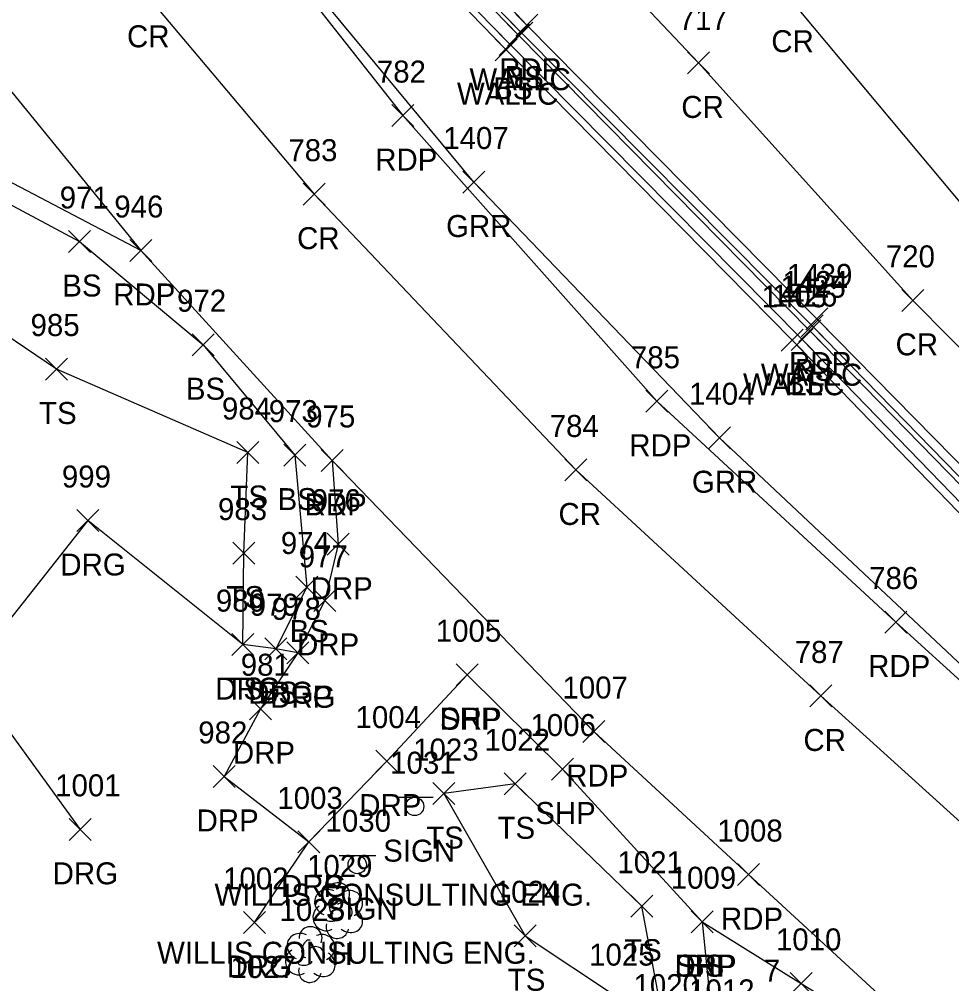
# Model space of a CAD drawing. Extents: x 1647133 to 1649138, y 411736 to 414924.
# Drawn here: x 1648689 to 1648773.8, y 411978.2 to 412065.9 of the extents above; entities that cross this region are included whole.
import ezdxf

# ---------------------------------------------------------------- set-up
doc = ezdxf.new("R2010")
doc.units = 0
for name, color, linetype in [('C_I', 7, 'Continuous'), ('L_A', 7, 'Continuous'), ('L_I', 7, 'Continuous'), ('L_TIC', 7, 'Continuous'), ('LELB', 7, 'Continuous'), ('LTD', 7, 'Continuous'), ('LW', 7, 'Continuous'), ('P_A', 7, 'Continuous'), ('P_I', 7, 'Continuous'), ('P_TIC', 7, 'Continuous'), ('PET', 7, 'Continuous'), ('PRC', 7, 'Continuous'), ('PSP', 7, 'Continuous'), ('R_A', 7, 'Continuous'), ('R_I', 7, 'Continuous'), ('R_TIC', 7, 'Continuous'), ('RDG', 7, 'Continuous'), ('RDP', 7, 'Continuous'), ('RGR', 7, 'Continuous'), ('S_A', 7, 'Continuous'), ('S_C', 7, 'Continuous'), ('S_I', 7, 'Continuous'), ('SSGN', 7, 'Continuous')]:
    doc.layers.add(name, color=color, linetype=linetype)

msp = doc.modelspace()

# ---------------------------------------------------------------- linework, layer by layer
at = {"layer": 'L_TIC'}
for points in [[(1648733.403, 412063.434), (1648735.403, 412065.434)], [(1648735.403, 412063.434), (1648733.403, 412065.434)], [(1648733.698, 412063.622), (1648735.698, 412065.622)], [(1648735.698, 412063.622), (1648733.698, 412065.622)], [(1648732.652, 412062.604), (1648734.652, 412064.604)], [(1648734.652, 412062.604), (1648732.652, 412064.604)], [(1648732.27, 412062.116), (1648734.27, 412064.116)], [(1648734.27, 412062.116), (1648732.27, 412064.116)], [(1648693.49, 412044.675), (1648695.49, 412046.675)], [(1648695.49, 412044.675), (1648693.49, 412046.675)], [(1648760.086, 412036.999), (1648762.086, 412038.999)], [(1648762.086, 412036.999), (1648760.086, 412038.999)], [(1648759.897, 412036.563), (1648761.897, 412038.563)], [(1648761.897, 412036.563), (1648759.897, 412038.563)], [(1648704.723, 412035.291), (1648706.723, 412037.291)], [(1648706.723, 412035.291), (1648704.723, 412037.291)], [(1648758.271, 412035.695), (1648760.271, 412037.695)], [(1648760.271, 412035.695), (1648758.271, 412037.695)], [(1648759.182, 412035.756), (1648761.182, 412037.756)], [(1648761.182, 412035.756), (1648759.182, 412037.756)], [(1648691.408, 412033.081), (1648693.408, 412035.081)], [(1648693.408, 412033.081), (1648691.408, 412035.081)], [(1648708.804, 412025.49), (1648710.804, 412027.49)], [(1648710.804, 412025.49), (1648708.804, 412027.49)], [(1648713.06, 412025.254), (1648715.06, 412027.254)], [(1648715.06, 412025.254), (1648713.06, 412027.254)], [(1648708.445, 412016.344), (1648710.445, 412018.344)], [(1648710.445, 412016.344), (1648708.445, 412018.344)], [(1648714.16, 412013.261), (1648716.16, 412015.261)], [(1648716.16, 412013.261), (1648714.16, 412015.261)], [(1648708.342, 412008.024), (1648710.342, 412010.024)], [(1648710.342, 412008.024), (1648708.342, 412010.024)], [(1648711.342, 412007.654), (1648713.342, 412009.654)], [(1648713.342, 412007.654), (1648711.342, 412009.654)], [(1648733.084, 411995.367), (1648735.084, 411997.367)], [(1648735.084, 411995.367), (1648733.084, 411997.367)], [(1648726.6, 411994.482), (1648728.6, 411996.482)], [(1648728.6, 411994.482), (1648726.6, 411996.482)], [(1648744.598, 411984.241), (1648746.598, 411986.241)], [(1648746.598, 411984.241), (1648744.598, 411986.241)], [(1648750.095, 411982.828), (1648752.095, 411984.828)], [(1648752.095, 411982.828), (1648750.095, 411984.828)], [(1648734.017, 411981.551), (1648736.017, 411983.551)], [(1648736.017, 411981.551), (1648734.017, 411983.551)], [(1648759.092, 411977.22), (1648761.092, 411979.22)], [(1648761.092, 411977.22), (1648759.092, 411979.22)]]:
    msp.add_lwpolyline(points, dxfattribs=at)
at = {"layer": 'LELB'}
for points in [[(1648695.678, 412105.565), (1648703.852, 412095.255), (1648710.046, 412087.718), (1648733.652, 412063.604), (1648760.182, 412036.756), (1648786.341, 412009.779), (1648811.728, 411984.211), (1648827.527, 411968.324), (1648831.218, 411963.386)], [(1648704.664, 412095.833), (1648711.149, 412088.766), (1648734.698, 412064.622), (1648761.086, 412037.999), (1648787.653, 412010.792), (1648812.355, 411985.321), (1648827.903, 411969.607)], [(1648661.044, 412062.283), (1648673.216, 412057.037), (1648694.49, 412045.675), (1648705.723, 412036.291), (1648714.06, 412026.254), (1648715.16, 412014.261), (1648712.342, 412008.654)], [(1648709.342, 412009.024), (1648709.445, 412017.344), (1648709.804, 412026.49), (1648692.408, 412034.081), (1648676.484, 412044.815), (1648662.935, 412050.112)], [(1648735.867, 411960.961), (1648741.091, 411963.551), (1648745.573, 411967.62), (1648747.716, 411974.063), (1648745.598, 411985.241), (1648734.084, 411996.367), (1648727.6, 411995.482), (1648735.017, 411982.551), (1648743.595, 411976.838)], [(1648751.095, 411983.828), (1648760.092, 411978.22), (1648771.973, 411970.92), (1648795.546, 411950.439), (1648830.258, 411918.417), (1648852.646, 411898.353), (1648868.763, 411879.164), (1648878.386, 411860.923), (1648891.378, 411855.434), (1648912.798, 411838.201), (1648926.61, 411828.098), (1648926.491, 411825.939), (1648922.273, 411828.096)]]:
    msp.add_lwpolyline(points, dxfattribs=at)
at = {"layer": 'LTD'}
for p, q in [((1648717.955, 411984.897), (1648717.955, 411984.897)), ((1648717.955, 411984.897), (1648717.955, 411984.897)), ((1648715.448, 411980.899), (1648715.448, 411980.899)), ((1648715.448, 411980.899), (1648715.448, 411980.899))]:
    msp.add_line(p, q, dxfattribs=at)
for centre in [(1648718.001, 411986.331), (1648715.494, 411982.333)]:
    msp.add_arc(centre, 1.047, 335.52715, 180.95627, dxfattribs=at)
for centre, major_axis, ratio, start_param, end_param in [((1648717.163, 411985.564), (1.21, -0.512), 0.895232, 1.570796, 4.712389), ((1648717.746, 411985.356), (-0.208, -0.792), 0.645439, 3.141593, 6.283185), ((1648718.996, 411985.481), (-1.141, -0.483), 0.949671, 1.570796, 4.712389), ((1648716.872, 411984.189), (0.584, -1.042), 0.959034, 3.141593, 6.283185), ((1648718.455, 411984.731), (-0.5, 0.667), 0.989748, 3.141593, 6.283185), ((1648718.955, 411984.064), (-1.09, 0.792), 0.841452, 1.570796, 4.712389), ((1648717.955, 411983.397), (0.265, 1.061), 0.942809, 1.570796, 4.712389), ((1648717.497, 411984.147), (-0.625, -0.083), 0.423636, 0, 3.141593), ((1648714.656, 411981.565), (1.21, -0.512), 0.895232, 1.570796, 4.712389), ((1648716.489, 411981.482), (-1.141, -0.483), 0.949671, 1.570796, 4.712389), ((1648715.239, 411981.357), (-0.208, -0.792), 0.645439, 3.141593, 6.283185), ((1648714.364, 411980.19), (0.584, -1.042), 0.959034, 3.141593, 6.283185), ((1648715.948, 411980.732), (-0.5, 0.667), 0.989748, 3.141593, 6.283185), ((1648716.448, 411980.066), (-1.09, 0.792), 0.841452, 1.570796, 4.712389), ((1648714.989, 411980.149), (-0.625, -0.083), 0.423636, 0, 3.141593), ((1648715.448, 411979.399), (0.265, 1.061), 0.942809, 1.570796, 4.712389)]:
    msp.add_ellipse(centre, major_axis=major_axis, ratio=ratio, start_param=start_param, end_param=end_param, dxfattribs=at)
at = {"layer": 'LW'}
for points in [[(1648830.392, 411963.284), (1648792.891, 412001.948), (1648759.271, 412036.695), (1648733.27, 412063.116), (1648709.494, 412087.59), (1648704.253, 412093.509), (1648697.556, 412102.144)], [(1648704.664, 412095.833), (1648710.908, 412088.591), (1648734.403, 412064.434), (1648760.897, 412037.563), (1648787.2, 412010.572), (1648812.273, 411985.189), (1648827.903, 411969.607)]]:
    msp.add_lwpolyline(points, dxfattribs=at)
at = {"layer": 'P_TIC'}
for points in [[(1648734.153, 412064.343), (1648736.153, 412066.343)], [(1648736.153, 412064.343), (1648734.153, 412066.343)], [(1648749.767, 412060.914), (1648751.767, 412062.914)], [(1648751.767, 412060.914), (1648749.767, 412062.914)], [(1648722.887, 412056.125), (1648724.887, 412058.125)], [(1648724.887, 412056.125), (1648722.887, 412058.125)], [(1648714.839, 412048.98), (1648716.839, 412050.98)], [(1648716.839, 412048.98), (1648714.839, 412050.98)], [(1648699.073, 412043.859), (1648701.073, 412045.859)], [(1648701.073, 412043.859), (1648699.073, 412045.859)], [(1648699.073, 412043.859), (1648701.073, 412045.859)], [(1648701.073, 412043.859), (1648699.073, 412045.859)], [(1648769.244, 412039.325), (1648771.244, 412041.325)], [(1648771.244, 412039.325), (1648769.244, 412041.325)], [(1648760.506, 412037.635), (1648762.506, 412039.635)], [(1648762.506, 412037.635), (1648760.506, 412039.635)], [(1648745.982, 412030.15), (1648747.982, 412032.15)], [(1648747.982, 412030.15), (1648745.982, 412032.15)], [(1648716.467, 412024.769), (1648718.467, 412026.769)], [(1648718.467, 412024.769), (1648716.467, 412026.769)], [(1648738.601, 412023.905), (1648740.601, 412025.905)], [(1648740.601, 412023.905), (1648738.601, 412025.905)], [(1648767.696, 412010.078), (1648769.696, 412012.078)], [(1648769.696, 412010.078), (1648767.696, 412012.078)], [(1648728.734, 412005.286), (1648730.734, 412007.286)], [(1648730.734, 412005.286), (1648728.734, 412007.286)], [(1648760.868, 412003.355), (1648762.868, 412005.355)], [(1648762.868, 412003.355), (1648760.868, 412005.355)], [(1648740.246, 412000.123), (1648742.246, 412002.123)], [(1648742.246, 412000.123), (1648740.246, 412002.123)], [(1648737.387, 411996.711), (1648739.387, 411998.711)], [(1648739.387, 411996.711), (1648737.387, 411998.711)], [(1648754.318, 411987.116), (1648756.318, 411989.116)], [(1648756.318, 411987.116), (1648754.318, 411989.116)], [(1648750.095, 411982.828), (1648752.095, 411984.828)], [(1648752.095, 411982.828), (1648750.095, 411984.828)]]:
    msp.add_lwpolyline(points, dxfattribs=at)
at = {"layer": 'PET'}
for points in [[(1648536.119, 412432.998), (1648543.399, 412417.954), (1648546.486, 412415.003), (1648562.248, 412380.849), (1648562.337, 412375.739), (1648565.289, 412369.171), (1648579.297, 412340.19), (1648594.414, 412306.778), (1648606.351, 412280.635), (1648620.629, 412249.259), (1648631.777, 412225.06), (1648641.267, 412204.566), (1648646.814, 412192.55), (1648664.816, 412155.812), (1648677.431, 412126.914), (1648681.854, 412118.139), (1648693.972, 412097.362), (1648709.507, 412075.411), (1648723.887, 412057.125), (1648746.982, 412031.15), (1648768.696, 412011.078), (1648794.521, 411987.621), (1648826.406, 411959.789)], [(1648512.544, 412422.792), (1648530.09, 412384.206), (1648549.578, 412341.858), (1648567.717, 412302.186), (1648584.888, 412264.911), (1648603.961, 412222.556), (1648616.989, 412192.513), (1648626.592, 412174.015), (1648634.702, 412156.346), (1648647.722, 412129.202), (1648659.195, 412106.441), (1648667.013, 412092.615), (1648674.657, 412079.411), (1648685.658, 412062.516), (1648700.073, 412044.859), (1648717.467, 412025.769), (1648741.246, 412001.123), (1648755.318, 411988.116), (1648772.85, 411971.957)], [(1648833.709, 411965.976), (1648813.189, 411986.13), (1648788.104, 412011.597), (1648761.506, 412038.635), (1648735.153, 412065.343), (1648710.962, 412091.103), (1648695.849, 412110.74)], [(1648700.073, 412044.859), (1648679.944, 412055.42), (1648661.723, 412064.182), (1648648.389, 412067.638), (1648630.86, 412074.167)]]:
    msp.add_lwpolyline(points, dxfattribs=at)
at = {"layer": 'PRC'}
for points in [[(1648523.855, 412428.164), (1648541.762, 412388.819), (1648560.786, 412347.218), (1648578.952, 412307.656), (1648596.522, 412268.849), (1648615.514, 412228.06), (1648629.383, 412198.525), (1648645.407, 412164.541), (1648659.578, 412134.14), (1648672.041, 412110.748), (1648683.898, 412091.11), (1648700.383, 412068.335), (1648715.839, 412049.98), (1648739.601, 412024.905), (1648761.868, 412004.355), (1648787.636, 411981.064), (1648820.993, 411950.624), (1648837.381, 411936.249), (1648865.129, 411910.894), (1648893.845, 411885.618), (1648930.35, 411852.903), (1648951.421, 411834.103), (1648988.1, 411800.425), (1649025.041, 411766.663)], [(1648664.816, 412155.812), (1648676.979, 412144.697), (1648692.804, 412127.015), (1648705.779, 412111.7), (1648725.575, 412089.279), (1648736.199, 412077.337), (1648750.767, 412061.914), (1648770.244, 412040.325), (1648787.372, 412023.03), (1648802.926, 412006.988), (1648820.913, 411988.588), (1648839.835, 411968.01), (1648856.098, 411949.207), (1648864.815, 411933.931), (1648873.225, 411921.132)], [(1648743.955, 412085.872), (1648758.948, 412067.89), (1648776.375, 412047.027), (1648792.583, 412027.973)]]:
    msp.add_lwpolyline(points, dxfattribs=at)
at = {"layer": 'PSP'}
msp.add_lwpolyline([(1648729.734, 412006.286), (1648738.387, 411997.711), (1648751.095, 411983.828)], dxfattribs=at)
at = {"layer": 'R_TIC'}
for points in [[(1648729.332, 412050.085), (1648731.332, 412052.085)], [(1648731.332, 412050.085), (1648729.332, 412052.085)], [(1648751.672, 412026.834), (1648753.672, 412028.834)], [(1648753.672, 412026.834), (1648751.672, 412028.834)], [(1648716.467, 412024.769), (1648718.467, 412026.769)], [(1648718.467, 412024.769), (1648716.467, 412026.769)], [(1648694.263, 412019.308), (1648696.263, 412021.308)], [(1648696.263, 412019.308), (1648694.263, 412021.308)], [(1648717.015, 412017.154), (1648719.015, 412019.154)], [(1648719.015, 412017.154), (1648717.015, 412019.154)], [(1648715.784, 412012.046), (1648717.784, 412014.046)], [(1648717.784, 412012.046), (1648715.784, 412014.046)], [(1648708.342, 412008.024), (1648710.342, 412010.024)], [(1648710.342, 412008.024), (1648708.342, 412010.024)], [(1648711.342, 412007.654), (1648713.342, 412009.654)], [(1648713.342, 412007.654), (1648711.342, 412009.654)], [(1648713.335, 412007.279), (1648715.335, 412009.279)], [(1648715.335, 412007.279), (1648713.335, 412009.279)], [(1648713.335, 412007.279), (1648715.335, 412009.279)], [(1648715.335, 412007.279), (1648713.335, 412009.279)], [(1648728.734, 412005.286), (1648730.734, 412007.286)], [(1648730.734, 412005.286), (1648728.734, 412007.286)], [(1648709.949, 412002.193), (1648711.949, 412004.193)], [(1648711.949, 412002.193), (1648709.949, 412004.193)], [(1648721.439, 411997.432), (1648723.439, 411999.432)], [(1648723.439, 411997.432), (1648721.439, 411999.432)], [(1648706.651, 411996.036), (1648708.651, 411998.036)], [(1648708.651, 411996.036), (1648706.651, 411998.036)], [(1648693.565, 411991.229), (1648695.565, 411993.229)], [(1648695.565, 411991.229), (1648693.565, 411993.229)], [(1648714.327, 411990.08), (1648716.327, 411992.08)], [(1648716.327, 411990.08), (1648714.327, 411992.08)], [(1648714.327, 411990.08), (1648716.327, 411992.08)], [(1648716.327, 411990.08), (1648714.327, 411992.08)], [(1648709.392, 411982.76), (1648711.392, 411984.76)], [(1648711.392, 411982.76), (1648709.392, 411984.76)], [(1648750.095, 411982.828), (1648752.095, 411984.828)], [(1648752.095, 411982.828), (1648750.095, 411984.828)]]:
    msp.add_lwpolyline(points, dxfattribs=at)
at = {"layer": 'RDG'}
for points in [[(1648714.335, 412008.279), (1648712.342, 412008.654), (1648709.342, 412009.024), (1648695.263, 412020.308), (1648684.257, 412006.407), (1648694.565, 411992.229)], [(1648710.392, 411983.76), (1648715.327, 411991.08)]]:
    msp.add_lwpolyline(points, dxfattribs=at)
at = {"layer": 'RDP'}
for points in [[(1648717.467, 412025.769), (1648718.015, 412018.154), (1648716.784, 412013.046), (1648714.335, 412008.279), (1648710.949, 412003.193), (1648707.651, 411997.036), (1648715.327, 411991.08), (1648722.439, 411998.432), (1648729.734, 412006.286)], [(1648751.095, 411983.828), (1648752.119, 411973.584), (1648770.231, 411969.569)]]:
    msp.add_lwpolyline(points, dxfattribs=at)
at = {"layer": 'RGR'}
msp.add_lwpolyline([(1648828.248, 411959.455), (1648783.912, 411998.445), (1648752.672, 412027.834), (1648730.332, 412051.085), (1648710.333, 412075.22), (1648699.799, 412090.248), (1648693.801, 412098.81), (1648690.054, 412105.682)], dxfattribs=at)
at = {"layer": 'SSGN'}
for p, q in [((1648723.314, 411995.141), (1648726.647, 411995.141)), ((1648724.961, 411994.308), (1648724.961, 411994.308)), ((1648718.09, 411989.861), (1648721.424, 411989.861)), ((1648719.737, 411989.028), (1648719.737, 411989.028))]:
    msp.add_line(p, q, dxfattribs=at)
for centre in [(1648724.961, 411994.308), (1648719.737, 411989.028)]:
    msp.add_circle(centre, 0.833, dxfattribs=at)

# ---------------------------------------------------------------- texts
at = {"layer": 'C_I'}
msp.add_text('7', height=2, dxfattribs=at).set_placement((1648756.703, 411978.39))
msp.add_text('7', height=2, dxfattribs=at).set_placement((1648756.703, 411978.39))
msp.add_text('7', height=2, dxfattribs=at).set_placement((1648756.703, 411978.39))
msp.add_text('7', height=2, dxfattribs=at).set_placement((1648756.703, 411978.39))
msp.add_text('7', height=2, dxfattribs=at).set_placement((1648756.703, 411978.39))
msp.add_text('7', height=2, dxfattribs=at).set_placement((1648756.703, 411978.39))
msp.add_text('7', height=2, dxfattribs=at).set_placement((1648756.703, 411978.39))
msp.add_text('7', height=2, dxfattribs=at).set_placement((1648756.703, 411978.39))
msp.add_text('7', height=2, dxfattribs=at).set_placement((1648756.703, 411978.39))
at = {"layer": 'L_A'}
for s, p in [('BS', (1648733.139, 412059.622)), ('WALLC', (1648729.939, 412059.434)), ('WALLC', (1648728.806, 412058.116)), ('BS', (1648732.093, 412058.604)), ('BS', (1648692.931, 412040.675)), ('WALLC', (1648756.432, 412032.563)), ('BS', (1648759.527, 412032.999)), ('WALLC', (1648754.807, 412031.695)), ('BS', (1648758.622, 412031.756)), ('BS', (1648704.164, 412031.291)), ('TS', (1648690.818, 412029.081)), ('TS', (1648708.213, 412021.49)), ('BS', (1648712.501, 412021.254)), ('TS', (1648707.855, 412012.344)), ('BS', (1648713.6, 412009.261)), ('TS', (1648707.752, 412004.024)), ('BS', (1648710.783, 412003.654)), ('TS', (1648732.493, 411991.367)), ('TS', (1648726.01, 411990.482)), ('H', (1648717.388, 411979.897)), ('TS', (1648744.007, 411980.241)), ('BS', (1648749.536, 411978.828)), ('TS', (1648733.426, 411977.551))]:
    msp.add_text(s, height=2, dxfattribs=at).set_placement(p)
at = {"layer": 'L_I'}
for s, p in [('971', (1648692.695, 412048.675)), ('1425', (1648758.204, 412040.563)), ('1424', (1648758.393, 412040.999)), ('1405', (1648756.5, 412039.695)), ('1426', (1648757.433, 412039.756)), ('972', (1648703.36, 412039.291)), ('985', (1648690.046, 412037.081)), ('984', (1648707.442, 412029.49)), ('973', (1648711.698, 412029.254)), ('983', (1648707.083, 412020.344)), ('974', (1648712.797, 412017.261)), ('980', (1648706.893, 412012.024)), ('979', (1648709.972, 412011.654)), ('1022', (1648731.312, 411999.367)), ('1023', (1648724.829, 411998.482)), ('1029', (1648715.175, 411987.897)), ('1021', (1648743.393, 411988.241)), ('1009', (1648748.237, 411986.828)), ('1024', (1648732.245, 411985.551)), ('1028', (1648712.676, 411983.899)), ('1010', (1648757.801, 411981.22)), ('1025', (1648740.823, 411979.838)), ('1027', (1648708.218, 411978.704)), ('1020', (1648744.857, 411977.063))]:
    msp.add_text(s, height=2, dxfattribs=at).set_placement(p)
at = {"layer": 'P_A'}
for s, p in [('CR', (1648698.816, 412063.335)), ('CR', (1648757.381, 412062.89)), ('RDP', (1648732.641, 412060.343)), ('CR', (1648749.2, 412056.914)), ('RDP', (1648721.375, 412052.125)), ('CR', (1648714.272, 412044.98)), ('RDP', (1648697.561, 412039.859)), ('RDP', (1648697.561, 412039.859)), ('CR', (1648768.677, 412035.325)), ('RDP', (1648758.994, 412033.635)), ('RDP', (1648744.47, 412026.15)), ('RDP', (1648714.955, 412020.769)), ('CR', (1648738.034, 412019.905)), ('RDP', (1648766.184, 412006.078)), ('SHP', (1648727.269, 412001.286)), ('CR', (1648760.301, 411999.355)), ('RDP', (1648738.735, 411996.123)), ('SHP', (1648735.923, 411992.711)), ('RDP', (1648752.806, 411983.116)), ('SHP', (1648748.631, 411978.828))]:
    msp.add_text(s, height=2, dxfattribs=at).set_placement(p)
at = {"layer": 'P_I'}
for s, p in [('717', (1648748.972, 412064.914)), ('782', (1648721.525, 412060.125)), ('783', (1648713.477, 412052.98)), ('946', (1648697.656, 412047.859)), ('946', (1648697.656, 412047.859)), ('720', (1648767.795, 412043.325)), ('1439', (1648758.805, 412041.635)), ('785', (1648744.619, 412034.15)), ('975', (1648715.105, 412028.769)), ('784', (1648737.238, 412027.905)), ('786', (1648766.279, 412014.078)), ('1005', (1648726.884, 412009.286)), ('787', (1648759.506, 412007.355)), ('1007', (1648738.396, 412004.123)), ('1006', (1648735.482, 412000.711)), ('1008', (1648752.468, 411991.116)), ('1009', (1648748.237, 411986.828))]:
    msp.add_text(s, height=2, dxfattribs=at).set_placement(p)
at = {"layer": 'R_A'}
for s, p in [('GRR', (1648727.82, 412046.085)), ('GRR', (1648750.16, 412022.834)), ('DRP', (1648714.955, 412020.769)), ('DRG', (1648692.751, 412015.308)), ('DRP', (1648715.503, 412013.154)), ('DRP', (1648714.272, 412008.046)), ('DRG', (1648706.83, 412004.024)), ('DRG', (1648709.83, 412003.654)), ('DRG', (1648711.823, 412003.279)), ('DRP', (1648711.823, 412003.279)), ('DRP', (1648727.222, 412001.286)), ('DRP', (1648708.437, 411998.193)), ('DRP', (1648719.927, 411993.432)), ('DRP', (1648705.139, 411992.036)), ('DRG', (1648692.053, 411987.229)), ('DRG', (1648712.815, 411986.08)), ('DRP', (1648712.815, 411986.08)), ('DRG', (1648707.88, 411978.76)), ('DRP', (1648748.584, 411978.828))]:
    msp.add_text(s, height=2, dxfattribs=at).set_placement(p)
at = {"layer": 'R_I'}
for s, p in [('1407', (1648727.56, 412054.085)), ('1404', (1648749.901, 412030.834)), ('975', (1648715.105, 412028.769)), ('999', (1648692.893, 412023.308)), ('976', (1648715.598, 412021.154)), ('977', (1648714.422, 412016.046)), ('980', (1648706.893, 412012.024)), ('979', (1648709.972, 412011.654)), ('978', (1648711.973, 412011.279)), ('978', (1648711.973, 412011.279)), ('1005', (1648726.884, 412009.286)), ('981', (1648709.154, 412006.193)), ('1004', (1648719.589, 412001.432)), ('982', (1648705.289, 412000.036)), ('1001', (1648692.281, 411995.229)), ('1003', (1648712.477, 411994.08)), ('1003', (1648712.477, 411994.08)), ('1002', (1648707.541, 411986.76)), ('1009', (1648748.237, 411986.828)), ('1012', (1648749.914, 411976.584)), ('1012', (1648749.914, 411976.584))]:
    msp.add_text(s, height=2, dxfattribs=at).set_placement(p)
at = {"layer": 'S_A'}
for p in [(1648722.099, 411989.288), (1648716.875, 411984.008)]:
    msp.add_text('SIGN', height=2, dxfattribs=at).set_placement(p)
at = {"layer": 'S_C'}
for p in [(1648706.768, 411985.288), (1648701.544, 411980.008)]:
    msp.add_text('WILLIS CONSULTING ENG.', height=2, dxfattribs=at).set_placement(p)
at = {"layer": 'S_I'}
for s, p in [('1031', (1648722.736, 411997.288)), ('1030', (1648716.859, 411992.008))]:
    msp.add_text(s, height=2, dxfattribs=at).set_placement(p)

doc.saveas('drawing.dxf')
